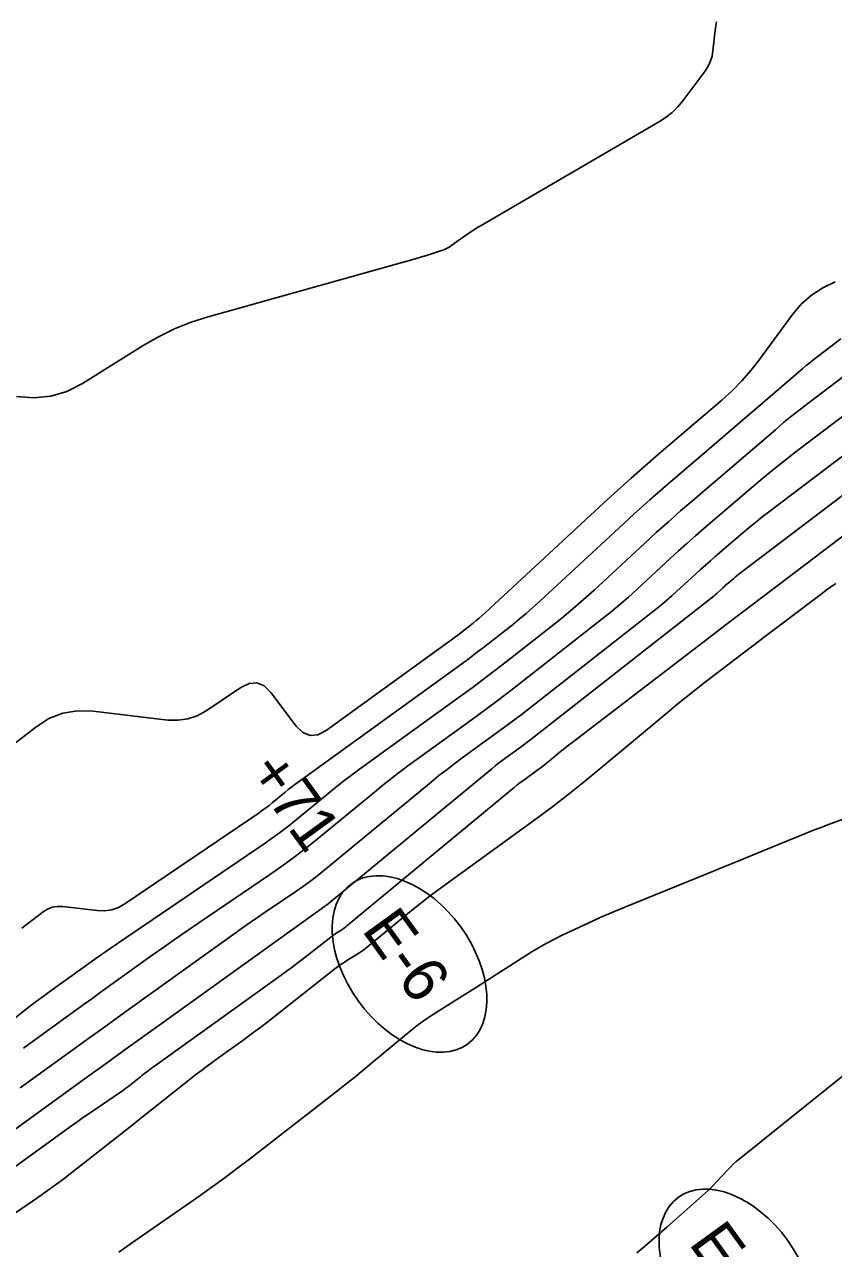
# Model space of a CAD drawing. Extents: x 1005228 to 1008882, y 1883389 to 1885754.
# Drawn here: x 1007802.3 to 1007914.3, y 1885078.7 to 1885248.1 of the extents above; entities that cross this region are included whole.
import ezdxf

# ---------------------------------------------------------------- set-up
doc = ezdxf.new("R2010")
doc.units = 0
for name, color, linetype in [('C-ANNO-NOTE', 7, 'Continuous'), ('R_Erosion', 7, 'Continuous'), ('S_BASELINE', 7, 'Continuous'), ('S_BRIDGE', 7, 'Continuous')]:
    doc.layers.add(name, color=color, linetype=linetype)

msp = doc.modelspace()

# ---------------------------------------------------------------- linework, layer by layer
at = {"layer": 'C-ANNO-NOTE'}
for points in [[(1007801.25, 1885196.64), (1007803.65, 1885196.43), (1007805.97, 1885196.67), (1007808.2, 1885197.33), (1007810.35, 1885198.42), (1007818.77, 1885203.67), (1007820.91, 1885204.9), (1007823.12, 1885205.97), (1007825.4, 1885206.89), (1007827.76, 1885207.64), (1007856.12, 1885215.6), (1007856.58, 1885215.73), (1007857.04, 1885215.87), (1007857.5, 1885216.01), (1007857.97, 1885216.15), (1007859.81, 1885216.73), (1007860.26, 1885216.89), (1007860.69, 1885217.08), (1007861.11, 1885217.31), (1007861.52, 1885217.57), (1007863.59, 1885219.04), (1007864.07, 1885219.38), (1007864.56, 1885219.7), (1007865.06, 1885220.01), (1007865.56, 1885220.31), (1007890.25, 1885234.67), (1007891.17, 1885235.27), (1007892.02, 1885235.95), (1007892.79, 1885236.71), (1007893.49, 1885237.56), (1007896.51, 1885241.6), (1007896.95, 1885242.26), (1007897.28, 1885242.97), (1007897.52, 1885243.71), (1007897.65, 1885244.49), (1007898, 1885247.7), (1007898.13, 1885248.49)], [(1007914.58, 1885212.48), (1007912.86, 1885211.68), (1007911.3, 1885210.66), (1007909.91, 1885209.43), (1007908.68, 1885207.98), (1007904.09, 1885201.74), (1007902.91, 1885200.22), (1007901.64, 1885198.78), (1007900.29, 1885197.4), (1007898.86, 1885196.11), (1007890.17, 1885188.67), (1007888.25, 1885187.01), (1007886.33, 1885185.32), (1007884.44, 1885183.61), (1007882.56, 1885181.89), (1007866.11, 1885166.67), (1007865.71, 1885166.3), (1007865.3, 1885165.95), (1007864.88, 1885165.6), (1007864.45, 1885165.26), (1007862.74, 1885163.91), (1007862.31, 1885163.58), (1007861.87, 1885163.25), (1007861.44, 1885162.92), (1007860.99, 1885162.6), (1007844.1, 1885150.39), (1007842.96, 1885149.79), (1007841.89, 1885149.69), (1007840.89, 1885150.1), (1007839.97, 1885151), (1007836.42, 1885155.66), (1007835.5, 1885156.57), (1007834.5, 1885156.98), (1007833.43, 1885156.91), (1007832.27, 1885156.35), (1007827.47, 1885153.12), (1007826.24, 1885152.43), (1007824.96, 1885151.99), (1007823.61, 1885151.8), (1007822.2, 1885151.84), (1007811.83, 1885153.06), (1007809.68, 1885153.12), (1007807.64, 1885152.77), (1007805.71, 1885152.03), (1007803.9, 1885150.87), (1007788.82, 1885139.29)], [(1007915.37, 1885204.6), (1007912.2, 1885202.2), (1007911.65, 1885201.78), (1007911.11, 1885201.35), (1007910.57, 1885200.91), (1007910.05, 1885200.47), (1007893.29, 1885186.12), (1007891.09, 1885184.22), (1007888.91, 1885182.3), (1007886.75, 1885180.36), (1007884.61, 1885178.39), (1007873.65, 1885168.25), (1007872.72, 1885167.41), (1007871.77, 1885166.58), (1007870.81, 1885165.78), (1007869.83, 1885164.99), (1007865.87, 1885161.89), (1007864.88, 1885161.12), (1007863.88, 1885160.36), (1007862.87, 1885159.61), (1007861.86, 1885158.87), (1007840.22, 1885143.23), (1007839.76, 1885142.89), (1007839.3, 1885142.55), (1007838.85, 1885142.2), (1007838.41, 1885141.84), (1007836.64, 1885140.38), (1007836.2, 1885140.02), (1007835.74, 1885139.67), (1007835.28, 1885139.34), (1007834.81, 1885139.01), (1007816.25, 1885126.39), (1007815.35, 1885125.89), (1007814.41, 1885125.56), (1007813.43, 1885125.41), (1007812.4, 1885125.45), (1007807.59, 1885126.02), (1007806.87, 1885126.03), (1007806.18, 1885125.92), (1007805.54, 1885125.67), (1007804.93, 1885125.28), (1007802.57, 1885123.47), (1007801.98, 1885123.03)], [(1007920.35, 1885197.44), (1007909.19, 1885188.99), (1007907.62, 1885187.78), (1007906.08, 1885186.55), (1007904.55, 1885185.3), (1007903.03, 1885184.03), (1007896.41, 1885178.36), (1007895.22, 1885177.33), (1007894.04, 1885176.29), (1007892.88, 1885175.24), (1007891.72, 1885174.18), (1007887.1, 1885169.91), (1007885.94, 1885168.85), (1007884.75, 1885167.82), (1007883.55, 1885166.81), (1007882.32, 1885165.83), (1007871.39, 1885157.26), (1007869.65, 1885155.91), (1007867.9, 1885154.58), (1007866.13, 1885153.26), (1007864.35, 1885151.96), (1007857.2, 1885146.8), (1007855.43, 1885145.5), (1007853.67, 1885144.16), (1007851.94, 1885142.8), (1007850.23, 1885141.41), (1007843.35, 1885135.74), (1007841.63, 1885134.35), (1007839.87, 1885133), (1007838.08, 1885131.69), (1007836.26, 1885130.42), (1007826.45, 1885123.76), (1007824.84, 1885122.65), (1007823.22, 1885121.54), (1007821.62, 1885120.41), (1007820.02, 1885119.27), (1007812.82, 1885114.1), (1007811.64, 1885113.25), (1007810.46, 1885112.4), (1007809.28, 1885111.55), (1007808.1, 1885110.7), (1007803.38, 1885107.29), (1007802.21, 1885106.43)], [(1007922.83, 1885193.86), (1007905.32, 1885180.59), (1007904.42, 1885179.9), (1007903.53, 1885179.19), (1007902.65, 1885178.47), (1007901.78, 1885177.74), (1007897.97, 1885174.47), (1007897.29, 1885173.88), (1007896.61, 1885173.29), (1007895.94, 1885172.68), (1007895.27, 1885172.07), (1007892.62, 1885169.61), (1007891.95, 1885169.01), (1007891.27, 1885168.41), (1007890.57, 1885167.83), (1007889.87, 1885167.27), (1007872.15, 1885153.39), (1007871.04, 1885152.52), (1007869.92, 1885151.67), (1007868.79, 1885150.83), (1007867.65, 1885150), (1007863.09, 1885146.7), (1007861.95, 1885145.86), (1007860.83, 1885145.01), (1007859.72, 1885144.14), (1007858.63, 1885143.25), (1007843.99, 1885131.18), (1007842.99, 1885130.38), (1007841.98, 1885129.6), (1007840.95, 1885128.85), (1007839.9, 1885128.12), (1007835.67, 1885125.24), (1007834.61, 1885124.52), (1007833.56, 1885123.79), (1007832.52, 1885123.06), (1007831.48, 1885122.31), (1007817.03, 1885111.94), (1007815.15, 1885110.59), (1007813.27, 1885109.24), (1007811.39, 1885107.88), (1007809.52, 1885106.53), (1007801.75, 1885100.92)], [(1007797.57, 1885092.71), (1007810.93, 1885102.36), (1007813.51, 1885104.22), (1007816.08, 1885106.07), (1007818.66, 1885107.93), (1007821.24, 1885109.78), (1007843.85, 1885126.02), (1007843.87, 1885126.04), (1007843.9, 1885126.05), (1007843.92, 1885126.07), (1007843.95, 1885126.09), (1007844.05, 1885126.15), (1007844.07, 1885126.17), (1007844.1, 1885126.19), (1007844.12, 1885126.21), (1007844.14, 1885126.23), (1007867.03, 1885145.09), (1007867.5, 1885145.48), (1007867.98, 1885145.86), (1007868.47, 1885146.23), (1007868.97, 1885146.59), (1007870.96, 1885148.03), (1007871.45, 1885148.39), (1007871.94, 1885148.76), (1007872.43, 1885149.13), (1007872.92, 1885149.51), (1007897.41, 1885168.71), (1007897.6, 1885168.85), (1007897.78, 1885169), (1007897.96, 1885169.16), (1007898.13, 1885169.32), (1007898.83, 1885169.96), (1007899, 1885170.12), (1007899.18, 1885170.28), (1007899.35, 1885170.44), (1007899.53, 1885170.59), (1007900.53, 1885171.45), (1007900.76, 1885171.64), (1007900.99, 1885171.83), (1007901.22, 1885172.01), (1007901.46, 1885172.19), (1007925.32, 1885190.28)], [(1007919.93, 1885180.55), (1007906.86, 1885170.65), (1007904.4, 1885168.79), (1007901.94, 1885166.92), (1007899.48, 1885165.04), (1007897.02, 1885163.17), (1007878.09, 1885148.7), (1007877.7, 1885148.4), (1007877.31, 1885148.09), (1007876.93, 1885147.78), (1007876.54, 1885147.47), (1007875.03, 1885146.2), (1007874.65, 1885145.89), (1007874.26, 1885145.58), (1007873.87, 1885145.28), (1007873.47, 1885144.99), (1007871.45, 1885143.51), (1007870.98, 1885143.17), (1007870.52, 1885142.82), (1007870.06, 1885142.45), (1007869.61, 1885142.09), (1007846.98, 1885123.33), (1007846.81, 1885123.19), (1007846.62, 1885123.05), (1007846.44, 1885122.92), (1007846.25, 1885122.8), (1007845.47, 1885122.32), (1007845.28, 1885122.2), (1007845.09, 1885122.07), (1007844.91, 1885121.94), (1007844.73, 1885121.8), (1007840.78, 1885118.7), (1007840.06, 1885118.14), (1007839.34, 1885117.59), (1007838.6, 1885117.05), (1007837.87, 1885116.51), (1007820.33, 1885103.94), (1007820.11, 1885103.78), (1007819.89, 1885103.62), (1007819.68, 1885103.45), (1007819.46, 1885103.28), (1007818.6, 1885102.61), (1007818.39, 1885102.44), (1007818.17, 1885102.27), (1007817.96, 1885102.1), (1007817.74, 1885101.93), (1007816.82, 1885101.21), (1007816.6, 1885101.03), (1007816.37, 1885100.86), (1007816.14, 1885100.69), (1007815.9, 1885100.53), (1007811.83, 1885097.75), (1007811.07, 1885097.24), (1007810.32, 1885096.71), (1007809.57, 1885096.18), (1007808.83, 1885095.65), (1007793.39, 1885084.5)]]:
    msp.add_lwpolyline(points, dxfattribs=at)
at = {"layer": 'R_Erosion'}
for centre in [(1007855.64, 1885118.07), (1007900.9, 1885074.68)]:
    msp.add_ellipse(centre, major_axis=(8.04, -11.09), ratio=0.638788, dxfattribs=at)
at = {"layer": 'S_BRIDGE'}
for points in [[(1007782.34, 1885095.68), (1007802.86, 1885112.03), (1007803.33, 1885112.4), (1007803.8, 1885112.77), (1007804.28, 1885113.12), (1007804.76, 1885113.47), (1007806.69, 1885114.87), (1007807.17, 1885115.22), (1007807.65, 1885115.56), (1007808.13, 1885115.91), (1007808.62, 1885116.26), (1007811.56, 1885118.37), (1007812.21, 1885118.84), (1007812.87, 1885119.3), (1007813.53, 1885119.76), (1007814.19, 1885120.21), (1007835.53, 1885134.72), (1007836.68, 1885135.51), (1007837.81, 1885136.34), (1007838.91, 1885137.19), (1007840, 1885138.06), (1007844.31, 1885141.61), (1007845.39, 1885142.49), (1007846.49, 1885143.36), (1007847.6, 1885144.2), (1007848.72, 1885145.03), (1007862.72, 1885155.14), (1007864.31, 1885156.3), (1007865.88, 1885157.47), (1007867.45, 1885158.67), (1007869.01, 1885159.87), (1007875.2, 1885164.73), (1007876.74, 1885165.96), (1007878.25, 1885167.22), (1007879.73, 1885168.51), (1007881.19, 1885169.83), (1007888.16, 1885176.28), (1007889.81, 1885177.8), (1007891.48, 1885179.29), (1007893.16, 1885180.78), (1007894.85, 1885182.24), (1007906.29, 1885192.03), (1007907.43, 1885193), (1007908.59, 1885193.95), (1007909.77, 1885194.88), (1007910.96, 1885195.79), (1007917.86, 1885201.02)], [(1007799.33, 1885082.44), (1007804.31, 1885085.83), (1007805.48, 1885086.65), (1007806.64, 1885087.48), (1007807.78, 1885088.34), (1007808.91, 1885089.21), (1007814.84, 1885093.88), (1007816.13, 1885094.89), (1007817.41, 1885095.91), (1007818.69, 1885096.92), (1007819.97, 1885097.93), (1007826.03, 1885102.7), (1007826.86, 1885103.34), (1007827.68, 1885103.97), (1007828.52, 1885104.59), (1007829.36, 1885105.2), (1007832.74, 1885107.63), (1007833.58, 1885108.24), (1007834.42, 1885108.86), (1007835.24, 1885109.48), (1007836.07, 1885110.12), (1007845.32, 1885117.39), (1007845.68, 1885117.67), (1007846.06, 1885117.94), (1007846.44, 1885118.2), (1007846.83, 1885118.45), (1007848.39, 1885119.41), (1007848.78, 1885119.66), (1007849.16, 1885119.92), (1007849.53, 1885120.2), (1007849.89, 1885120.49), (1007855.34, 1885125), (1007856.37, 1885125.85), (1007857.42, 1885126.67), (1007858.48, 1885127.48), (1007859.55, 1885128.27), (1007873.34, 1885138.3), (1007875.47, 1885139.88), (1007877.57, 1885141.49), (1007879.65, 1885143.14), (1007881.7, 1885144.83), (1007891.29, 1885152.85), (1007892.61, 1885153.94), (1007893.94, 1885155.02), (1007895.29, 1885156.08), (1007896.64, 1885157.13), (1007902.63, 1885161.71), (1007903.72, 1885162.54), (1007904.8, 1885163.36), (1007905.89, 1885164.19), (1007906.98, 1885165.01), (1007911.34, 1885168.31), (1007912.43, 1885169.13), (1007913.53, 1885169.94), (1007914.64, 1885170.74)], [(1007815.39, 1885078.18), (1007817.17, 1885079.42), (1007818.94, 1885080.66), (1007826.32, 1885085.8), (1007828.13, 1885087.08), (1007829.92, 1885088.38), (1007831.7, 1885089.71), (1007833.47, 1885091.06), (1007845.7, 1885100.55), (1007846.89, 1885101.47), (1007848.07, 1885102.41), (1007849.24, 1885103.36), (1007850.4, 1885104.32), (1007856.01, 1885108.99), (1007856.69, 1885109.54), (1007857.39, 1885110.07), (1007858.11, 1885110.57), (1007858.84, 1885111.04), (1007861.81, 1885112.9), (1007862.55, 1885113.37), (1007863.29, 1885113.84), (1007864.03, 1885114.3), (1007864.77, 1885114.78), (1007872.47, 1885119.69), (1007873.5, 1885120.31), (1007874.54, 1885120.91), (1007875.6, 1885121.47), (1007876.68, 1885121.99), (1007881.05, 1885124.03), (1007882.14, 1885124.53), (1007883.24, 1885125.01), (1007884.34, 1885125.49), (1007885.46, 1885125.95), (1007898.28, 1885131.16), (1007899.64, 1885131.71), (1007900.99, 1885132.26), (1007902.34, 1885132.81), (1007903.7, 1885133.36), (1007910.22, 1885136.02), (1007911.02, 1885136.34), (1007911.82, 1885136.66), (1007912.62, 1885136.96), (1007913.42, 1885137.27), (1007916.64, 1885138.46)], [(1007924.96, 1885110.07), (1007901.3, 1885091.07), (1007900.87, 1885090.71), (1007900.46, 1885090.34), (1007900.06, 1885089.95), (1007899.67, 1885089.54), (1007898.15, 1885087.9), (1007897.76, 1885087.5), (1007897.37, 1885087.1), (1007896.97, 1885086.72), (1007896.55, 1885086.34), (1007891.26, 1885081.64), (1007890.23, 1885080.74), (1007889.2, 1885079.84), (1007888.16, 1885078.95), (1007887.12, 1885078.07)]]:
    msp.add_lwpolyline(points, dxfattribs=at)

# ---------------------------------------------------------------- texts
at = {"layer": 'R_Erosion'}
for p in [(1007848.92, 1885122.78), (1007894.19, 1885079.39)]:
    msp.add_text('E-6', height=6.25, rotation=305.9673, dxfattribs=at).set_placement(p)
at = {"layer": 'S_BASELINE'}
msp.add_text('+71', height=6.25, rotation=305.9673, dxfattribs=at).set_placement((1007833.08, 1885144.61))

doc.saveas('drawing.dxf')
